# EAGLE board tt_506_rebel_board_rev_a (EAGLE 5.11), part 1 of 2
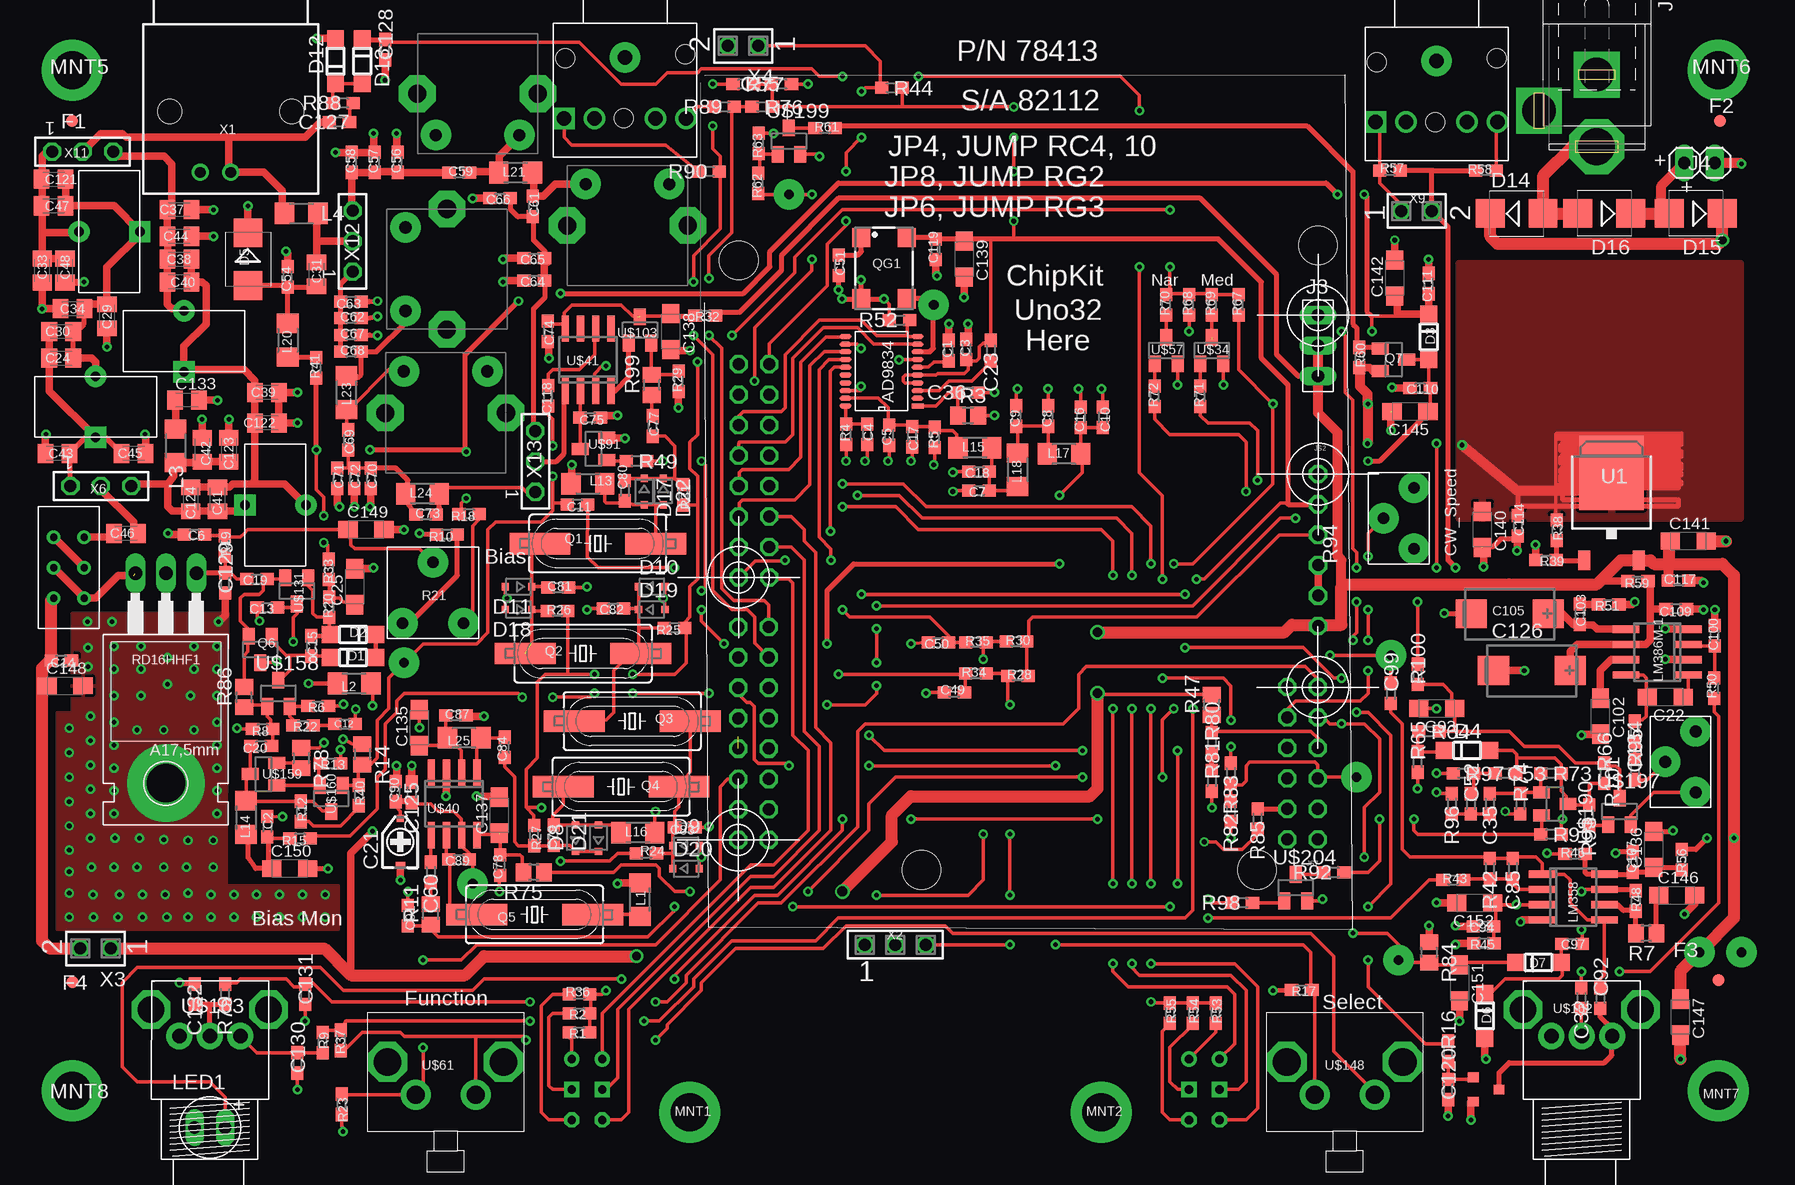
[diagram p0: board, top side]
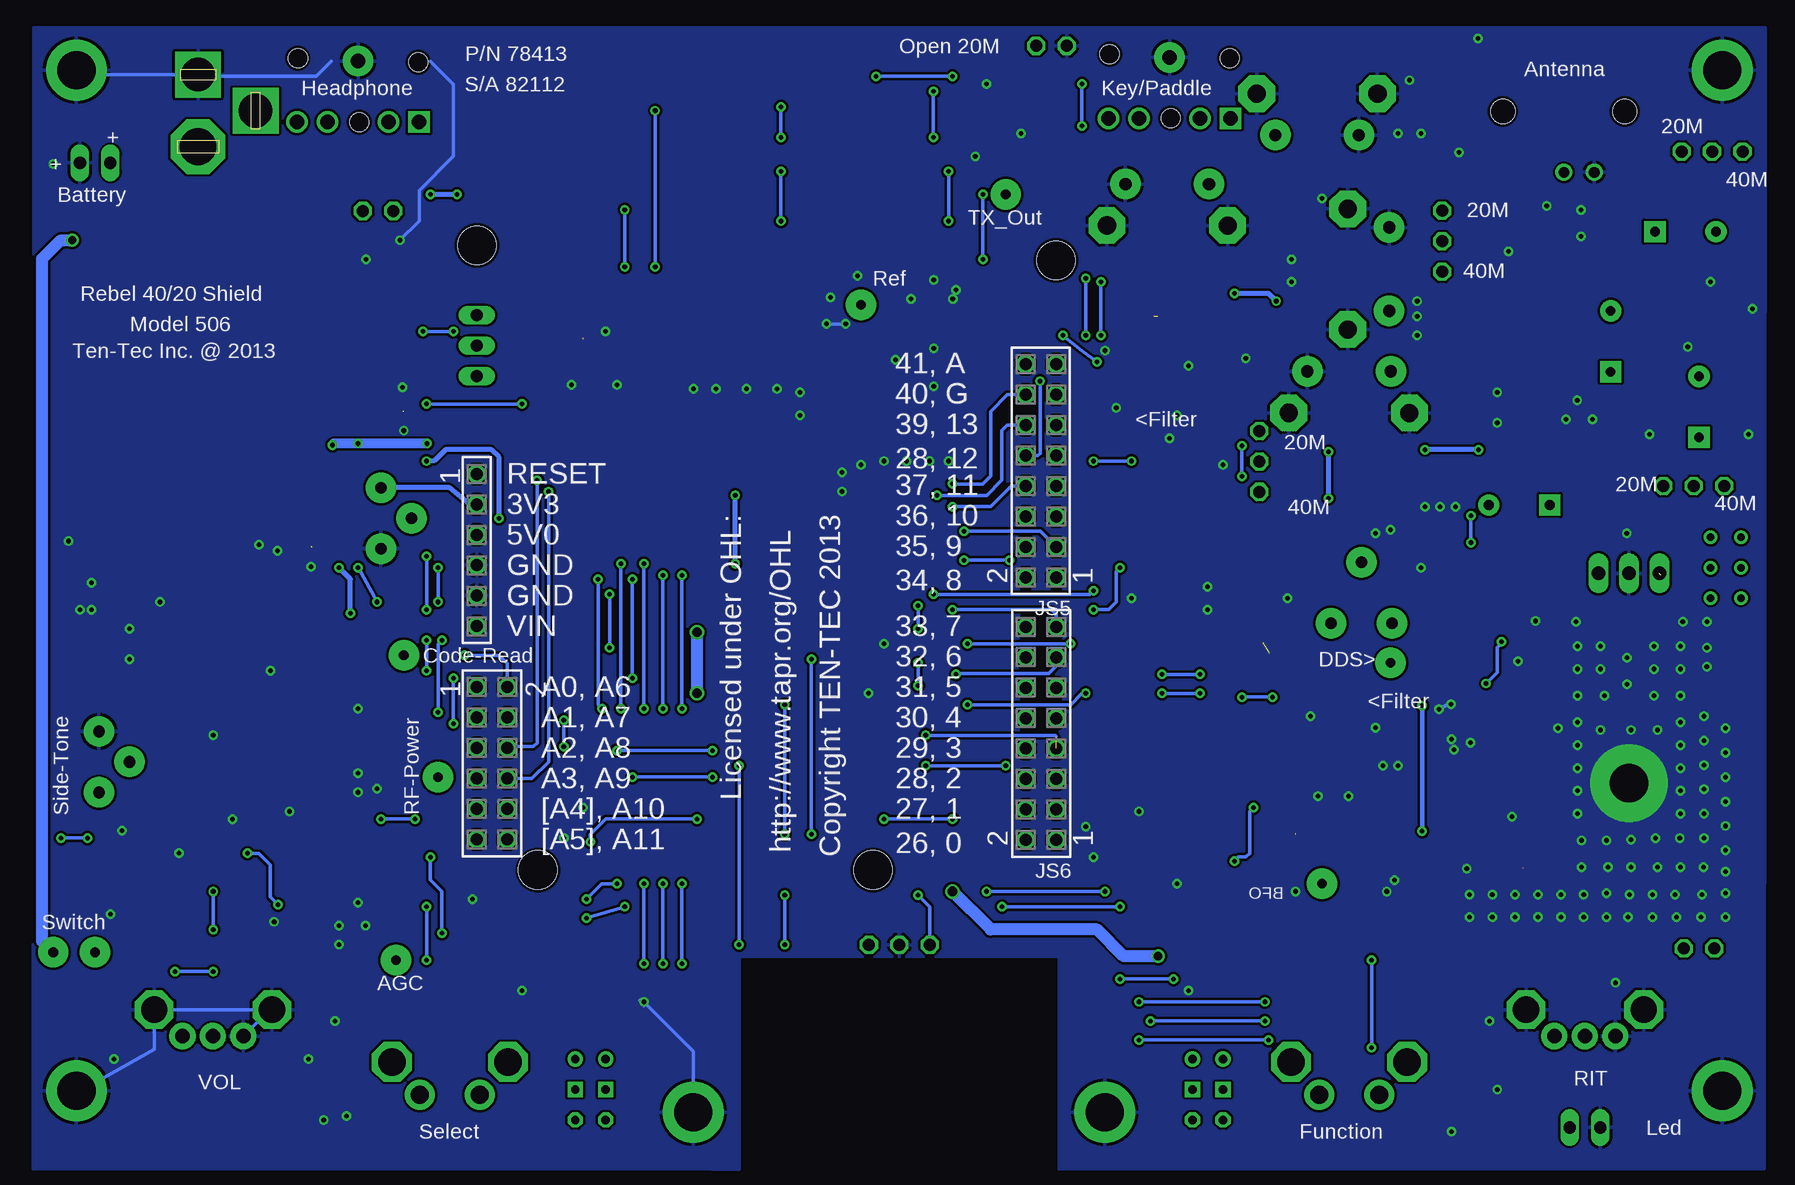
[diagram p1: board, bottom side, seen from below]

No outline drawn. Coordinates in mm, seen from the top.
Copper layers (1*16): Top 0.035mm / dielectric 1.5mm / Bottom 0.035mm
Design rules "default *": minimum track width 10mil, minimum drill 12mil, track to track 8mil, track to pad 8mil, pad to pad 8mil, via to via 8mil, smd to smd 7mil, copper to edge 10mil, drill to drill 10mil, minimum pad ring 10mil, minimum via ring 8mil, stop-mask expansion 4mil, vias tented up to drill 16mil, thermal gap 10mil
Holes 3.2 mm at 59.32,76.09 74.56,25.29 102.5,25.29 107.58,77.36

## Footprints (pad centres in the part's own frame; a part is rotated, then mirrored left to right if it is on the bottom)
0603 = smd 1.1 x 1: 1 -0.85,0; 2 0.85,0
CTRIMCTZ3 = smd 0.6 x 0.6: 1 0,1.95 | smd 0.78 x 0.6: 2 0,-1.95
SMC_A = smd 1.6 x 1.4: + -1.5,0; - 1.5,0
C0805K = smd 1.3 x 1.6: 1 -1,0; 2 1,0
POL-7343 = smd 2.6 x 2.4: + 3.2,0; - -3.2,0
SOD123 = smd 1.4 x 1.4: A 1.9,0; C -1.9,0
SMB = smd 2.4 x 2.4: A 2.2,0; C -2.2,0
SOD323-R = smd 0.6 x 0.6: A 1.1,0; C -1.1,0
FIDUCIAL-1MM = smd 1 x 1: FID 0,0
SPC4077 = drill 2.794 pad 3.81 square: 1 -3,0 | drill 2.8 pad 3.81 square: 2 0,-4.8 | drill 3.048 pad 4.572 octagon: 3 3,0
SOCKET-1X3-.1IN = drill 1.016 long: 1 -2.54,0; 2 0,0; 3 2.54,0
PINS-1X2-.1IN = drill 1.016 long: 1 -1.27,0; 2 1.27,0
SSW-106-02-S-S = drill 1 pad 1.5 octagon: 1 -6.35,0; 2 -3.81,0; 3 -1.27,0; 4 1.27,0; 5 3.81,0; 6 6.35,0
SSW-108-02-S-D = drill 1 pad 1.5 octagon: 1 -8.89,-1.27; 2 -8.89,1.27; 3 -6.35,-1.27; 4 -6.35,1.27; 5 -3.81,-1.27; 6 -3.81,1.27; 7 -1.27,-1.27; 8 -1.27,1.27; 9 1.27,-1.27; 10 1.27,1.27; 11 3.81,-1.27; 12 3.81,1.27; 13 6.35,-1.27; 14 6.35,1.27; 15 8.89,-1.27; 16 8.89,1.27
SSW-106-02-S-D = drill 1 pad 1.5 octagon: 1 -6.35,-1.27; 2 -6.35,1.27; 3 -3.81,-1.27; 4 -3.81,1.27; 5 -1.27,-1.27; 6 -1.27,1.27; 7 1.27,-1.27; 8 1.27,1.27; 9 3.81,-1.27; 10 3.81,1.27; 11 6.35,-1.27; 12 6.35,1.27
1206 = smd 1.6 x 1.8: 1 -1.4,0; 2 1.4,0
LED-.1IN = drill 1.016 long: A 1.27,0; C -1.27,0
SO08 = smd 0.6 x 2.2: 1 -1.905,-2.6; 2 -0.635,-2.6; 3 0.635,-2.6; 4 1.905,-2.6; 5 1.905,2.6; 6 0.635,2.6; 7 -0.635,2.6; 8 -1.905,2.6
MOUNTINGHOLE-.125IN = drill 3.175 pad 5.08 round: MNT 0,0
SM49 = smd 5.08 x 1.778: 1 -4.826,0; 2 4.826,0
SOT23 = smd 1 x 1.4: 1 -0.95,-1.1; 2 0.95,-1.1; 3 0,1.1
CRYSTAL_SM77H = smd 1.6 x 1.5: 1 -2.55,-1.9; 2 2.55,-1.9; 3 2.55,1.9; 4 -2.55,1.9
R0805 = smd 1.3 x 1.5: 1 -0.85,0; 2 0.85,0
RVM-06-HP03-1 = drill 0.965 pad 2.54 round: 1 -2.54,-2.54; 2 0,2.54; 3 2.54,-2.54
RVM-06-VP01-1 = drill 0.965 pad 2.54 round: 1 -2.54,-1.27; 2 0,1.27; 3 2.54,-1.27
TO-220S = drill 1.118 long: 1 -3.81,-10.16; 2 -1.27,-10.16; 3 1.27,-10.16
TOROID = drill 0.8 pad 1.778 square: P$1 0,-2.54 | drill 0.8 pad 1.778 round: P$2 0,2.54
TO252 = smd 1 x 1.6: 1 -2.28,-5.039; 3 2.28,-5.039 | smd 0.025 x 0.025: 2 0,2.261 | smd 5.4 x 6.2: 4 0,2.261
AD9834 = smd 1 x 0.406: 1 -3,2.9; 2 -3,2.25; 3 -3,1.625; 4 -3,0.975; 5 -3,0.325; 6 -3,-0.325; 7 -3,-0.975; 8 -3,-1.625; 9 -3,-2.25; 10 -3,-2.9; 11 3,-2.9; 12 3,-2.25; 13 3,-1.625; 14 3,-0.975; 15 3,-0.325; 16 3,0.325; 17 3,0.975; 18 3,1.625; 19 3,2.25; 20 3,2.9
MIKE_SOT23 = smd 1 x 1.4: 1 -0.95,-1.1; 2 0.95,-1.1; 3 0,1.1
OUT_TRI = drill 0.6 round: CLF -1.27,2.54; CLS 1.27,2.54; GRF -1.27,0; GRS 1.27,0; RDF -1.27,-2.54; RDS 1.27,-2.54
TL1105JA = drill 1.5 pad 2.5 round: 1 -2.504,0; 2 2.494,-0.01 | drill 2.3 pad 3.3 octagon: 3 -4.843,2.741; 4 4.831,2.741
10MM_CAN = drill 1.016 pad 2.54 round: 1 -3.48,3.454; 2 3.48,3.454 | drill 1.5 pad 3.048 octagon: 3 -5.029,0 | drill 1.524 pad 3.048 octagon: 4 5.029,0
35252 = drill 1.2 pad 1.778 square: 1 -5.08,5.08 | drill 1.2 pad 1.778 round: 2 -5.08,2.54; 3 -5.08,-2.54 | drill 1.2 round: 4 -5.08,-5.08 | drill 1.2 pad 2.54 round: 5 0,0 | hole 1.575: 0.254,-5.004; -0.076,5.004; -5.08,0.102
3RP/1610N = drill 1.2 pad 2.184 round: 1 -2.54,0; 2 0,0; 3 2.54,0 | drill 2.2 pad 3 octagon: 4 -4.91,2.2; 5 4.89,2.2
GYR_LED_TL = drill 0.7 pad 1.27 round: P$1 -1.27,2.54; P$2 1.27,2.54 | drill 0.7 pad 1.27 square: P$3 -1.27,0; P$4 1.27,0 | drill 0.7 pad 1.27 octagon: P$5 -1.27,-2.54; P$6 1.27,-2.54
PAD = drill 0.8 pad 2.54 round: P$1 0,0
SOT23' = smd 0.813 x 0.889: 1 -1.016,-1.079; 2 1.016,-1.079; 3 0,1.079
AMP_227161 = drill 0.9 pad 1.27 round: 1 0,-5.08; 2 -2.54,-5.08 | hole 2: -5.08,0; 5.08,0
SSW-103-02-S-S = drill 1 pad 1.5 octagon: 1 -2.54,0; 2 0,0; 3 2.54,0
SSW-101-02-S-D = drill 1 pad 1.5 octagon: 1 0,-1.27; 2 0,1.27
TSW-103-02-S-S = drill 1 pad 1.5 octagon: 1 2.54,0; 2 0,0; 3 -2.54,0

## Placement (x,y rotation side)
C1  .1uf  [0603]  76.8,68.58 90 top
C2  .1uf  [0603]  20.03,28.89 90 top
C3  .1uf  [0603]  78.3,68.68 90 top
C4  27pf  [0603]  70.01,61.59 270 top
C5  3.3pf  [0603]  71.85,61.53 270 top
C6  .1uf  [0603]  13.96,53.26 180 top
C7  tbd  [0603]  79.34,56.9 180 top
C8  3.3pf  [0603]  85.12,63.12 90 top
C9  62pf  [0603]  82.45,63.12 90 top
C10  68pf  [0603]  89.66,63.02 90 top
C11  .01uf  [0603]  45.88,55.75 0 top
C12  .01uf  [0603]  26.5,37.45 0 top
C13  .01uf  [0603]  20.02,47.16 180 top
C14  .1uf  [0603]  2.86,42.75 0 top
C15  .01uf  [0603]  23.69,43.95 270 top
C16  dni  [0603]  87.82,63.02 90 top
C17  27pf  [0603]  73.76,61.4 270 top
C18  56pf  [0603]  79.34,58.48 180 top
C19  .1uf  [0603]  19.16,49.54 180 top
C20  .1uf  [0603]  19.53,35.62 0 top
C21  2-10pf  [CTRIMCTZ3]  31.11,27.62 0 top
C22  10uf  [SMC_A]  136.53,39.69 180 top
C23  .01uf  [0603]  80.33,68.58 90 top
C24  100pf  [C0805K]  2.86,67.94 0 top
C25  10uf  [SMC_A]  27.3,48.9 90 top
C29  820pf  [C0805K]  6.67,71.44 270 top
C30  15pf  [C0805K]  2.86,70.17 0 top
C31  .01uf  [C0805K]  24.13,74.93 270 top
C32  .1uf  [0603]  129.54,14.61 90 top
C33  dni  [C0805K]  1.27,75.25 270 top
C34  dni  [C0805K]  3.81,72.07 180 top
C35  .01uf  [0603]  121.92,30.8 90 top
C36  .1uf  [0603]  78.42,65.09 0 top
C37  120pf  [C0805K]  12.7,80.33 0 top
C38  3.3pf  [C0805K]  12.7,76.2 180 top
C39  330pf  [C0805K]  20,65.09 0 top
C40  62  [C0805K]  12.7,74.3 180 top
C41  39pf  [C0805K]  15.88,56.2 90 top
C42  180pf  [C0805K]  14.61,60.33 90 top
C43  470pf  [C0805K]  2.54,60.01 180 top
C44  dni  [C0805K]  12.7,78.11 0 top
C45  dni  [C0805K]  8.89,60.01 0 top
C46  .1uf  [C0805K]  8.26,53.34 0 top
C47  120pf  [C0805K]  2.22,80.64 180 top
C48  470pf  [C0805K]  3.17,75.25 270 top
C49  .047uf  [0603]  77.28,40.1 180 top
C50  .047uf  [0603]  75.95,44.23 180 top
C51  .1uf  [0603]  67.66,75.69 270 top
C52  .01uf  [0603]  120.33,30.8 270 top
C53  .01uf  [0603]  123.19,33.34 180 top
C54  220pf  [0603]  21.73,74.73 90 top
C55  .1uf  [0603]  62.87,90.81 0 top
C56  DNI  [0603]  30.89,84.28 90 top
C57  DNI  [0603]  28.98,84.28 90 top
C58  470pf  [0603]  27.08,84.28 90 top
C59  120pf  [0603]  36.02,83.41 0 top
C60  .1uf  [0603]  33.66,25.08 90 top
C61  120pf  [0603]  42.17,80.59 270 top
C62  820pf  [0603]  27.01,71.29 0 top
C63  DNI  [0603]  27.01,72.68 0 top
C64  120pf  [0603]  42.28,74.43 180 top
C65  120pf  [0603]  42.28,76.27 180 top
C66  120pf  [0603]  39.42,81.29 180 top
C67  DNI  [0603]  27.01,69.89 0 top
C68  220pf  [0603]  27.01,68.49 0 top
C69  220pf  [0603]  26.77,61.13 270 top
C70  DNI  [0603]  28.66,57.93 270 top
C71  DNI  [0603]  25.87,57.93 270 top
C72  820pf  [0603]  27.27,57.93 270 top
C73  560pf  [0603]  33.27,54.91 0 top
C74  .1uf  [0603]  43.41,70.19 270 top
C75  .1uf  [0603]  46.94,62.99 0 top
C77  680pf  [0603]  52.15,62.29 270 top
C78  .1uf  [0603]  39.45,25.69 270 top
C79  82pf  [0603]  43.89,28.19 90 top
C80  82pf  [0603]  49.83,56.9 270 top
C81  10pf  [0603]  44.27,48.83 0 top
C82  27pf  [0603]  48.87,47.1 180 top
C83  10pf  [0603]  54.81,28.82 0 top
C84  68pf  [0603]  39.8,35.5 270 top
C85  dni  [0603]  123.83,25.4 90 top
C87  .1uf  [0603]  35.74,38.15 0 top
C89  33pf  [0603]  36,26.15 180 top
C90  56pf  [0603]  30.72,31.82 90 top
C91  .01uf  [0603]  31.74,21.47 90 top
C92  .1uf  [0603]  131.13,14.61 270 top
C93  10uf  [SMC_A]  117.47,38.73 180 top
C94  .1uf  [0603]  121.37,20.59 180 top
C97  .1uf  [0603]  128.76,19.14 180 top
C99  .1uf  [0603]  113.67,40.01 270 top
C100  2200pf  [0603]  140.65,44.81 90 top
C102  1uf  [SMC_A]  131.13,38.1 270 top
C103  .047uf  [0603]  129.39,46.6 90 top
C105  100uf  [POL-7343]  123.56,46.65 0 top
C107  .1uf  [0603]  133.83,25.95 90 top
C109  .1uf  [0603]  137.44,47.06 0 top
C110  .1uf  [0603]  116.11,65.47 180 top
C111  .1uf  [0603]  116.81,74.17 90 top
C114  .1uf  [0603]  124.24,53.98 270 top
C117  .1uf  [0603]  137.64,49.4 0 top
C118  .01uf  [0603]  43.43,64.8 90 top
C119  .1uf  [0603]  75.72,77.03 270 top
C120  .1uf  [0603]  118.43,6.99 270 top
C121  22pf  [C0805K]  2.22,82.87 180 top
C122  dni  [C0805K]  20,62.55 0 top
C123  68pf  [C0805K]  16.83,60.33 90 top
C124  12pf  [C0805K]  13.65,56.2 90 top
C125  33pf  [0603]  32.07,31.75 90 top
C126  100uf  [POL-7343]  125.41,41.91 0 top
C127  3.3pf  [0603]  26.04,87.63 0 top
C128  .1uf  [0603]  29.84,93.66 270 top
C129  22pf  [0603]  16.51,49.21 270 top
C130  .1uf  [0603]  22.54,9.21 270 top
C131  .1uf  [0603]  23.18,14.92 270 top
C132  .1uf  [0603]  13.97,14.92 90 top
C133  270pf  [C0805K]  13.34,64.45 0 top
C134  .1uf  [0603]  133.99,36.83 90 top
C135  10uf  [SMC_A]  32.7,37.15 90 top
C136  10uf  [SMC_A]  135.57,26.99 90 top
C137  10uf  [SMC_A]  39.37,29.84 90 top
C138  10uf  [SMC_A]  53.66,70.17 270 top
C139  10uf  [SMC_A]  78.11,76.2 270 top
C140  10uf  [SMC_A]  121.28,53.66 270 top
C141  10uf  [SMC_A]  138.43,52.7 0 top
C142  10uf  [SMC_A]  113.98,74.61 90 top
C145  4.7uf  [SMC_A]  115.25,63.5 180 top
C146  10uf  [SMC_A]  137.48,23.18 0 top
C147  10uf  [SMC_A]  137.79,13.02 270 top
C148  10uf  [SMC_A]  3.17,40.64 0 top
C149  10uf  [SMC_A]  28.26,53.66 0 top
C150  10uf  [SMC_A]  21.91,25.4 0 top
C151  10uf  [SMC_A]  119.38,15.88 270 top
C152  10uf  [SMC_A]  120.65,22.54 180 top
D1  MMSD914T1  [SOD123]  27.18,43 0 top
D2  MMSD914T1  [SOD123]  27.18,44.91 180 top
D3  MMSD914T1  [SOD123]  116.81,69.72 270 top
D4  MMSD914T1  [SOD123]  120.02,35.24 0 top
D5  1N4007  [SMB]  18.41,76.2 270 top
D6  MMSD914T1  [SOD123]  121.49,13.12 270 top
D7  MMSD914T1  [SOD123]  125.96,17.57 0 top
D8  BB132  [SOD323-R]  45.72,27.94 90 top
D9  BB132  [SOD323-R]  54.93,27.3 0 top
D10  BB132  [SOD323-R]  52.07,48.9 0 top
D11  BB132  [SOD323-R]  40.96,48.9 180 top
D12  MMSD914T1  [SOD123]  25.72,92.71 90 top
D13  MMSD914T1  [SOD123]  27.94,92.71 270 top
D14  1N4007  [SMB]  124.14,80.01 0 top
D15  1N4007  [SMB]  139.06,80.01 180 top
D16  dni  [SMB]  131.44,80.01 180 top
D17  BB132  [SOD323-R]  51.44,56.83 270 top
D18  BB132  [SOD323-R]  40.96,46.99 180 top
D19  BB132  [SOD323-R]  52.07,46.99 0 top
D20  BB132  [SOD323-R]  54.93,25.4 0 top
D21  BB132  [SOD323-R]  47.62,27.94 90 top
D22  BB132  [SOD323-R]  53.02,56.83 270 top
F1  FIDUCIAL1MM  [FIDUCIAL-1MM]  3.77,87.72 0 top
F2  FIDUCIAL1MM  [FIDUCIAL-1MM]  141.08,87.74 0 top
F3  FIDUCIAL1MM  [FIDUCIAL-1MM]  140.98,16.09 0 top
F4  FIDUCIAL1MM  [FIDUCIAL-1MM]  3.78,15.93 90 top
J1  [SPC4077]  130.81,88.58 270 top
J3  CONNECTOR-3SOCKET-SIL3-.1IN  [SOCKET-1X3-.1IN]  107.59,68.99 270 top
J4  CONNECTOR-2PINS-SIL2-.1IN  [PINS-1X2-.1IN]  139.38,84.23 0 top
JS2  SSW-106-02-S-S  [SSW-106-02-S-S]  107.59,51.96 270 bottom
JS5  SSW-108-02-S-D  [SSW-108-02-S-D]  60.57,58.56 90 bottom
JS6  SSW-108-02-S-D  [SSW-108-02-S-D]  60.55,36.66 90 bottom
JS7  SSW-106-02-S-D  [SSW-106-02-S-D]  106.31,34.18 270 bottom
L1  15uh  [1206]  51.08,22.82 270 top
L2  47uh  [1206]  27.27,40.83 0 top
L3  1.8uh  [1206]  12.38,60.64 90 top
L4  1uh  [1206]  22.86,80.01 180 top
L13  6.8uh  [1206]  46.74,57.48 180 top
L14  47uh  [1206]  18.26,29.65 90 top
L15  1.8uh  [1206]  78.99,60.48 0 top
L16  6.8uh  [1206]  50.91,28.41 0 top
L17  2.7uh  [1206]  86.42,59.98 0 top
L18  5.6uh  [1206]  82.55,58.64 90 top
L20  100uh  [1206]  21.74,69.44 90 top
L21  18uh  [1206]  40.72,83.41 0 top
L23  27uh  [1206]  26.64,65.07 270 top
L24  3.9uh  [1206]  32.96,56.65 0 top
L25  4.7uh  [1206]  36.44,36.31 0 top
LED1  [LED-.1IN]  15.24,3.81 0 top
LM358  LM358D  [SO08]  128.86,23.03 270 top
LM386M-1  LM386M-1  [SO08]  135.86,43.45 90 top
MNT1  MOUNTINGHOLE.125IN  [MOUNTINGHOLE-.125IN]  55.24,5.08 0 top
MNT2  MOUNTINGHOLE.125IN  [MOUNTINGHOLE-.125IN]  89.53,5.08 0 top
MNT5  MOUNTINGHOLE.125IN  [MOUNTINGHOLE-.125IN]  3.78,91.95 0 top
MNT6  MOUNTINGHOLE.125IN  [MOUNTINGHOLE-.125IN]  140.94,91.95 0 top
MNT7  MOUNTINGHOLE.125IN  [MOUNTINGHOLE-.125IN]  140.94,6.86 0 top
MNT8  MOUNTINGHOLE.125IN  [MOUNTINGHOLE-.125IN]  3.78,6.86 0 top
Q1  9.00mhz  [SM49]  47.58,52.49 180 top
Q2  9.00mhz  [SM49]  46.34,43.33 0 top
Q3  9.00mhz  [SM49]  50.44,37.69 0 top
Q4  9.00mhz  [SM49]  49.51,32.22 180 top
Q5  9.00mhz  [SM49]  42.31,21.56 180 top
Q6  MMBT3906LT1  [SOT23]  19.45,43.66 180 top
Q7  MMBT3906LT1  [SOT23]  113.89,67.82 270 top
QG1  CRYSTAL_SM77H  [CRYSTAL_SM77H]  71.41,75.44 270 top
R1  180  [0603]  46.04,11.75 180 top
R2  180  [0603]  46.04,13.34 180 top
R3  6.8k  [R0805]  78.42,63.18 0 top
R4  220  [0603]  68.29,61.59 90 top
R5  220  [0603]  75.66,61.34 90 top
R6  100  [0603]  24.28,38.94 180 top
R7  2.2k  [R0805]  134.94,20 180 top
R8  1k  [0603]  19.64,37.05 0 top
R9  100  [0603]  24.64,10.89 270 top
R10  270  [0603]  35.01,53.25 0 top
R11  560  [R0805]  33.66,21.59 90 top
R12  330  [0603]  22.83,30.16 270 top
R13  27  [0603]  25.3,34.16 180 top
R14  560  [R0805]  27.94,34.92 270 top
R15  33  [0603]  22.76,27.91 0 top
R16  10k  [0603]  118.43,10.16 270 top
R17  10k  [0603]  106.24,15.27 180 top
R18  470  [0603]  36.85,54.97 0 top
R19  220  [0603]  16.47,52.3 270 top
R20  1k  [0603]  25.21,47.19 90 top
R21  1k_TP  [RVM-06-HP03-1]  33.85,48.4 0 top
R22  10  [0603]  23.02,37.33 180 top
R23  10k  [0603]  26.23,5.75 270 top
R24  100k  [0603]  51.61,26.68 180 top
R25  100k  [0603]  53.96,45.47 0 top
R26  100k  [0603]  44.21,46.86 0 top
R27  100k  [0603]  42.27,28.16 90 top
R28  10k  [0603]  82.58,41.47 0 top
R29  1.5k  [0603]  54.31,66.01 90 top
R30  10k  [0603]  82.45,44.32 0 top
R31  100k  [0603]  54.69,56.55 90 top
R32  1k  [0603]  56.52,71.51 180 top
R33  220  [0603]  25.16,50.34 90 top
R34  100k  [0603]  79.09,41.66 0 top
R35  100k  [0603]  79.09,44.26 0 top
R36  180  [0603]  46.04,14.92 180 top
R37  10k  [0603]  26.16,11.08 270 top
R38  220  [0603]  127.48,53.59 270 top
R39  1.2k  [0603]  126.59,51.12 180 top
R40  180  [0603]  27.65,31.5 270 top
R41  470  [0603]  24.11,67.14 90 top
R42  100k  [0603]  121.92,25.4 90 top
R43  10k  [0603]  118.86,24.45 0 top
R44  10k  [0603]  72.07,90.49 180 top
R45  100k  [0603]  121.41,19.16 180 top
R46  100k  [0603]  129.02,26.61 0 top
R47  12k  [R0805]  98.74,39.05 90 top
R48  100k  [0603]  134.07,22.71 270 top
R49  10k  [0603]  50.8,59.37 180 top
R50  10k  [0603]  140.6,40.44 270 top
R51  10  [0603]  131.82,47.4 180 top
R52  DNI  [0603]  72.71,71.12 0 top
R53  180  [0603]  99.06,13.34 270 top
R54  180  [0603]  97.16,13.34 270 top
R55  180  [0603]  95.25,13.34 270 top
R56  100  [0603]  137.9,26.14 270 top
R57  100  [0603]  113.58,83.59 180 top
R58  100  [0603]  121.58,83.59 0 top
R59  100  [0603]  134.25,49.36 180 top
R60  1.5k  [0603]  111.03,68.01 270 top
R61  1.5k  [0603]  66.52,87.12 0 top
R62  1.5k  [0603]  60.96,82.52 90 top
R63  10k  [0603]  60.99,85.85 90 top
R64  10k  [0603]  116.84,36.83 180 top
R65  10k  [0603]  115.89,34.29 270 top
R66  10k  [0603]  131.44,33.34 270 top
R67  10k  [0603]  100.97,72.39 270 top
R68  1meg  [0603]  96.84,72.39 90 top
R69  4.7k  [0603]  98.74,72.39 90 top
R70  100  [0603]  94.93,72.39 90 top
R71  1k  [0603]  97.79,64.77 90 top
R72  1k  [0603]  93.98,64.77 90 top
R73  330k  [0603]  127,33.34 180 top
R74  100k  [0603]  124.46,30.8 270 top
R75  820  [R0805]  42.23,25.08 180 top
R76  10k  [0603]  61.28,88.9 180 top
R77  10k  [0603]  59.69,90.81 180 top
R78  1  [R0805]  22.86,34.61 270 top
R79  1k  [0603]  16.51,14.92 90 top
R80  1.5k  [0603]  98.74,35.88 270 top
R81  1.5k  [0603]  98.74,32.7 270 top
R82  10k  [0603]  100.33,30.16 90 top
R83  10k  [0603]  100.33,33.34 90 top
R84  150k  [R0805]  116.84,18.41 270 top
R85  180  [0603]  102.55,29.53 90 top
R86  3.3k  [R0805]  18.1,39.69 90 top
R88  1k  [0603]  26.35,89.22 0 top
R89  1k  [0603]  58.1,88.9 0 top
R90  1k  [0603]  56.83,83.5 0 top
R91  180  [0603]  127,28.26 180 top
R92  33  [0603]  108.9,25.08 0 top
R93  10k  [0603]  130.18,29.84 90 top
R94  10k_RT_TP  [RVM-06-VP01-1]  114.3,54.61 90 top
R95  10k  [0603]  133.99,33.66 270 top
R96  10k  [0603]  118.75,30.8 90 top
R97  10k  [0603]  119.7,33.34 180 top
R98  1k  [0603]  101.28,22.54 0 top
R99  47  [R0805]  52.07,65.72 90 top
R100  100  [0603]  115.89,41.59 270 top
R101  1k_RT_TP  [RVM-06-VP01-1]  137.79,34.29 90 top
RD16HHF1  TO220S  [TO-220S]  10.31,39.85 180 top
TOROID1  TOROIDGREEN  [TOROID]  6.86,78.5 90 top
TOROID2  TOROIDRED  [TOROID]  5.72,63.89 0 top
TOROID3  TOROIDBLACK  [TOROID]  13.09,69.35 0 top
TOROID4  TOROIDWHITE  [TOROID]  20.71,55.7 270 top
U1  LM1117DTX-ADJ  [TO252]  132.05,56.13 0 top
U$1  AD9834  [AD9834]  71.22,66.87 180 top
U$34  MMBT3904  [MIKE_SOT23]  98.74,68.58 0 top
U$35  [CROSS_HAIR]  59.28,27.79 0 top
U$37  OUT_TRI  [OUT_TRI]  3.49,50.48 0 top
U$40  SA612  [SO08]  35.59,30.8 180 top
U$41  SA612  [SO08]  46.77,67.82 0 top
U$56  [ARROW<--]  72.28,8.08 270 top
U$57  MMBT3904  [MIKE_SOT23]  94.93,68.58 0 top
U$60  [CROSS_HAIR]  107.59,71.53 0 top
U$61  TACT_SWITCH  [TL1105JA]  34.89,6.54 0 top
U$63  [CROSS_HAIR]  107.59,58.29 0 top
U$64  [CROSS_HAIR]  107.56,40.51 0 top
U$69  21058  [10MM_CAN]  37.55,90 180 top
U$70  21058  [10MM_CAN]  50.04,79.01 0 top
U$80  21057  [10MM_CAN]  35,75.37 90 top
U$81  21057  [10MM_CAN]  34.89,63.39 0 top
U$91  MMBT3904  [MIKE_SOT23]  47.21,60.39 90 top
U$103  MMBT3904  [MIKE_SOT23]  51.09,70.29 0 top
U$131  MMBT3904  [MIKE_SOT23]  22.48,48.55 180 top
U$143  35252R  [35252]  49.85,93.03 90 top
U$148  TACT_SWITCH  [TL1105JA]  109.82,6.54 0 top
U$157  [CROSS_HAIR]  59.3,49.68 0 top
U$158  MMBT3904  [MIKE_SOT23]  20.95,40.01 0 top
U$159  MMBT3904  [MIKE_SOT23]  19.72,33.27 90 top
U$160  MMBT3904  [MIKE_SOT23]  25.37,31.24 180 top
U$162  EVUE25POT  [3RP/1610N]  129.57,11.43 0 top
U$163  EVUE25POT  [3RP/1610N]  15.24,11.43 0 top
U$166  GYR_LED_TL  [GYR_LED_TL]  46.67,6.99 0 top
U$168  GYR_LED_TL  [GYR_LED_TL]  98.11,6.99 0 top
U$173  PAD  [PAD]  142.88,18.41 0 top
U$174  PAD  [PAD]  139.38,18.41 0 top
U$176  2N7002  [SOT23']  121.6,6.99 270 top
U$177  PAD  [PAD]  63.5,81.6 0 top
U$183  PAD  [PAD]  114.3,17.78 90 top
U$184  PAD  [PAD]  113.67,43.18 90 top
U$185  PAD  [PAD]  31.43,42.55 90 top
U$186  PAD  [PAD]  75.56,72.39 90 top
U$187  PAD  [PAD]  37.15,24.13 90 top
U$188  35252R  [35252]  117.47,92.71 90 top
U$190  MMBT3904  [MIKE_SOT23]  127.32,30.8 270 top
U$191  PAD  [PAD]  110.81,33.02 0 top
U$197  MMBT3904  [MIKE_SOT23]  132.72,30.16 0 top
U$199  MMBT3904  [MIKE_SOT23]  63.5,86.04 0 top
U$204  MMBT3904  [MIKE_SOT23]  105.73,23.81 0 top
X1  1-227161-0  [AMP_227161]  16.99,88.52 0 top
X2  SSW-103-02-S-S  [SSW-103-02-S-S]  72.36,19.05 0 top
X3  SSW-101-02-S-D  [SSW-101-02-S-D]  5.71,18.73 90 top
X4  SSW-101-02-S-D  [SSW-101-02-S-D]  59.69,93.98 90 top
X6  TSW-103-02-S-S  [TSW-103-02-S-S]  6.17,57.29 180 top
X9  SSW-101-02-S-D  [SSW-101-02-S-D]  115.81,80.23 270 top
X11  TSW-103-02-S-S  [TSW-103-02-S-S]  4.64,85.17 180 top
X12  TSW-103-02-S-S  [TSW-103-02-S-S]  27.13,77.7 270 top
X13  TSW-103-02-S-S  [TSW-103-02-S-S]  42.37,59.35 270 top

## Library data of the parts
C1-C20 C23 C32 C35 C36 C49-C75 C77-C85 C87 C89-C92 C94 C97 C99 C100 C103 C105 C107 C109-C111 C114 C117-C120 C125-C132 C134 D1-D4 D6 D7 D12 D13 F1-F4 J3 J4 L1-L4 L13-L18 L20 L21 L23-L25 LED1 MNT1 MNT2 MNT5-MNT8 Q6 Q7 R1 R2 R4-R6 R8-R10 R12 R13 R15-R46 R48-R74 R76 R77 R79-R83 R85 R88-R98 R100 R101 U1 = mike
C21 C22 C24 C25 C29-C31 C33 C34 C37-C48 C93 C102 C121-C124 C133 C135-C142 C145-C152 = rcl
D5 D8-D11 D14-D22 = diode
J1 = con-jack; OC_FARNELL: unknown; OC_NEWARK: unknown
JS2 = con-samtec; MPN: SSW-106-02-S-S; OC_FARNELL: unknown; OC_NEWARK: 11P9416
JS5 JS6 = con-samtec; MPN: SSW-108-02-S-D; OC_FARNELL: unknown; OC_NEWARK: 85K7646
JS7 = con-samtec; MPN: SSW-106-02-S-D; OC_FARNELL: unknown; OC_NEWARK: 11P9414
LM358 LM386M-1 = linear
Q1-Q5 = crystal; OC_FARNELL: unknown; OC_NEWARK: unknown
QG1 = ethernetaudioboard_revd
R3 R7 R11 R14 R47 R75 R78 R84 R86 R99 = resistor
RD16HHF1 TOROID1-TOROID4 U$1 U$37 U$40 U$41 U$69 U$70 U$80 U$81 U$143 U$158 U$166 U$168 U$173 U$174 U$176 U$177 U$183-U$188 U$191 = rebel_506
U$34 U$57 U$91 U$103 U$131 U$159 U$160 U$190 U$197 U$199 U$204 = model506_Rebel
U$35 U$60 U$63 U$64 U$157 = CROSS_HAIR
U$56 = marks
U$61 U$148 = switch
U$162 U$163 = pot
X1 = con-coax; MF: TYCO ELECTRONICS; MPN: 1-227161; OC_FARNELL: unknown; OC_NEWARK: 33B3200
X2 = con-samtec; MPN: SSW-103-02-S-S; OC_FARNELL: unknown; OC_NEWARK: 11P9367
X3 X4 X9 = con-samtec; MPN: SSW-101-02-S-D; OC_FARNELL: unknown; OC_NEWARK: 82P1456
X6 X11-X13 = con-samtec; OC_FARNELL: unknown; OC_NEWARK: unknown

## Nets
+3.3V: C3.1 C23.2 C55.1 C119.1 C139.+ JS2.2 QG1.4 R9.1 R37.1 R44.1 R76.1 R77.1 R94.3 U$1.4 U$1.5
+5.0V: JS2.3 R28.2 R30.2
+8.0V: C114.1 C140.+ Q7.2 R38.1 R60.2 R67.2 R75.1 R100.1 U1.2 U1.4
+12V: C117.1 C141.+ C147.+ J3.2 J3.3 JS2.6 L2.2 R32.1 R47.2 R56.1 R59.2 U1.3 U$174.P$1 X3.1
BAND_DETECT: JS5.16 R44.2 X4.1
BAND_END_FLASH_LED: JS7.10 R85.2
BATTERY: JS7.5 R47.1 R80.1
CODE_READ: C99.1 JS7.2 U$184.P$1
CW_SPEED: JS7.4 R94.2
ENC_A: C50.1 JS6.15 R35.1
ENC_B: C49.1 JS6.13 R34.1
FSYNC: JS5.3 U$1.15
GND: C1.2 C2.2 C3.2 C4.2 C5.2 C6.2 C7.2 C8.2 C9.2 C10.2 C12.2 C13.2 C14.2 C16.2 C17.2 C18.2 C21.2 C25.- C29.2 C33.2 C34.2 C36.2 C37.2 C39.2 C42.2 C43.2 C44.2 C45.2 C48.2 C49.2 C50.2 C51.2 C54.2 C55.2 C56.2 C57.2 C58.2 C62.2 C63.2 C64.2 C65.2 C66.2 C67.2 C70.2 C71.2 C72.2 C74.2 C75.2 C78.2 C81.2 C82.2 C83.2 C87.2 C90.2 C91.2 C93.- C94.2 C100.2 C102.- C107.2 C109.2 C110.2 C111.2 C114.2 C117.2 C119.2 C120.2 C122.2 C123.2 C125.2 C126.- C128.2 C129.2 C130.2 C131.2 C132.2 C133.2 C135.- C136.- C137.- C138.- C139.- C140.- C141.- C142.- C145.- C146.- C147.- C148.- C149.- C150.- C151.- C152.- D5.C D6.A D9.A D10.A D11.A D12.A D18.A D19.A D20.A J1.1 J4.2 JS2.4 JS2.5 L1.1 L13.2 L16.2 LED1.C LM358.4 LM386M-1.2 LM386M-1.4 MNT1.MNT MNT2.MNT MNT5.MNT MNT6.MNT MNT7.MNT MNT8.MNT Q6.3 QG1.2 R1.1 R2.1 R3.2 R4.1 R5.1 R6.1 R8.1 R10.1 R13.1 R14.1 R17.2 R23.2 R29.1 R36.1 R39.2 R45.2 R51.1 R52.1 R53.1 R54.1 R55.1 R63.2 R65.2 R68.1 R74.2 R78.1 R81.2 R82.1 R84.1 R91.1 R94.1 R96.2 R97.2 R101.3 RD16HHF1.2 U$1.7 U$1.12 U$1.18 U$34.2 U$40.3 U$41.3 U$57.2 U$69.2 U$69.3 U$69.4 U$70.2 U$70.3 U$70.4 U$80.2 U$80.3 U$80.4 U$81.2 U$81.3 U$81.4 U$91.2 U$143.5 U$162.1 U$162.4 U$162.5 U$163.1 U$163.4 U$163.5 U$176.2 U$188.5 U$199.2 U$204.2 X1.2 X2.2 X4.2
LCD_D1: JS6.6
LCD_D2: JS6.8
LCD_D3: JS6.10
LCD_D4: JS6.12
LCD_EN: JS6.4
LCD_RS: JS6.2
MEDIUM_A8: JS7.6 R71.1
MP_A: JS5.8 U$168.P$2
MP_B: JS5.12 U$168.P$4
MP_C: JS5.14 U$168.P$6
N$1: C127.1 L4.2 X1.1 X11.2
N$2: JS5.1 U$1.14
N$3: JS5.5 U$1.13
N$4: JS5.7 U$1.11
N$5: JS5.9 U$1.9
N$6: C36.1 R3.1 U$1.1
N$7: C7.1 C18.1 L15.2 L18.1
N$8: C5.1 C17.1 L15.1 R5.2 U$1.19
N$9: C4.1 R4.2 U$1.20
N$10: C1.1 U$1.6
N$11: C8.1 C9.1 L17.1 L18.2
N$12: C20.1 L14.2 R12.1 U$159.3 U$160.3
N$13: C10.1 C11.2 C16.1 L17.2
N$14: C20.2 R8.2 R86.1 U$158.1
N$15: R78.2 U$159.2
N$16: R13.2 U$159.1 U$160.2
N$17: C11.1 C118.1 R14.2 R40.1 U$160.1 U$185.P$1
N$18: R6.2 R22.2 U$158.2
N$19: C12.1 R22.1
N$20: C2.1 C150.+ L14.1 R15.1
N$21: C15.2 D1.C Q6.1 U$158.3
N$22: D1.A D2.C
N$23: C15.1 D2.A R20.1 U$131.1
N$24: C25.+ R20.2 R33.1
N$25: C32.2 R50.2
N$26: C13.1 L2.1 U$131.3
N$27: C19.1 Q6.2 R86.2 U$131.2
N$28: C46.1 U$37.CLS
N$29: R30.1 R35.2 X2.1
N$30: C6.1 C149.+ R19.1 R21.2
N$31: C19.2 C129.1 R19.2 RD16HHF1.1
N$32: R18.2 R21.3
N$33: R10.2 R21.1
N$34: R80.2 R81.1
N$35: U$37.CLF U$37.GRS
N$36: C46.2 X6.2
N$37: C24.1 C30.1 C43.1 C45.1 TOROID2.P$1 X6.1
N$38: C24.2 C29.1 C30.2 C34.1 C47.1 C121.1 TOROID1.P$1 TOROID2.P$2
N$39: C33.1 C47.2 C48.1 C121.2 TOROID1.P$2 X11.1
N$40: C41.1 C42.1 C123.1 C124.1 L3.1 TOROID4.P$1 X6.3
N$41: C38.1 C39.1 C40.1 C41.2 C122.1 C124.2 TOROID3.P$1 TOROID4.P$2
N$42: C37.1 C38.2 C40.2 C44.1 TOROID3.P$2 X11.3
N$43: R38.2 R39.1 U1.1
N$44: D4.C R64.2 R65.1
N$45: JS6.11 R17.1 U$148.1
N$46: C130.1 R9.2 U$163.3
N$47: C93.+ R64.1 R66.1 R100.2 U$197.3
N$48: R61.1 U$199.3
N$49: C100.1 LM386M-1.3 R50.1
N$50: C35.2 R73.2 R74.1 U$190.1
N$51: C31.1 L4.1 X12.2
N$52: C31.2 C54.1 D5.A L20.2
N$53: L20.1 R41.2
N$54: R1.2 U$166.P$1
N$55: C61.2 C64.1 C65.1 C66.1 X13.3
N$56: C56.1 C57.1 C58.1 C59.1 X12.3
N$57: C59.2 L21.1 U$69.1
N$58: C61.1 L21.2 U$70.1
N$59: C62.1 C63.1 C67.1 C68.1 X12.1
N$60: C68.2 L23.1 U$80.1
N$61: C69.1 L23.2 U$81.1
N$62: C69.2 C70.1 C71.1 C72.1 C73.1 L24.1
N$63: C73.2 L24.2 X13.1
N$64: U$41.1 X13.2
N$65: C80.2 D17.A D22.A L13.1 Q1.1
N$66: U$41.4 U$103.1
N$67: R29.2 R99.2 U$103.2
N$68: C74.1 C138.+ R32.2 U$41.8 U$103.3
N$69: C75.1 U$41.2 U$91.3
N$70: C127.2 R88.2
N$71: C83.1 D9.C D20.C Q3.2 Q4.1 R24.1
N$72: R24.2 R25.2 R26.2 R27.2 R31.1 R67.1 R68.2 R69.2 R70.2
N$73: C81.1 D11.C D18.C Q1.2 Q2.1 R26.1
N$74: C79.2 D8.A D21.A L16.1 Q4.2
N$75: C77.2 C80.1 D17.C D22.C R31.2
N$76: C79.1 C84.2 D8.C D21.C R27.1
N$77: C60.1 R11.2
N$78: C14.1 C148.+ U$37.RDF X3.2
N$79: JS6.5 R23.1 U$61.1
N$80: QG1.3 U$1.8 U$186.P$1
N$81: C84.1 L25.2 U$40.1
N$82: C21.1 C89.1 C90.1 C125.1 U$40.7 U$187.P$1
N$83: C78.1 C137.+ R75.2 U$40.8
N$84: C89.2 Q5.2 U$40.6
N$85: R12.2 R40.2
N$86: C60.2 U$40.5
N$87: C85.1 LM358.2 R42.1 R43.2
N$88: C51.1 QG1.1
N$89: LM358.6 R7.2 R48.2
N$90: C91.1 R11.1 R43.1
N$91: C85.2 C92.1 C99.2 LM358.1 LM358.5 R42.2
N$92: C94.1 C152.+ LM358.3 R45.1 R46.1
N$93: C97.1 LM358.7 R48.1
N$94: C146.+ R7.1
N$95: C97.2 D6.C D7.A
N$96: R49.2 U$91.1
N$97: C92.2 U$162.3 U$176.3
N$98: R28.1 R34.2 X2.3
N$99: R37.2 U$61.2 U$148.2
N$100: C103.1 C105.+ LM386M-1.5
N$101: C22.- C134.2 LM386M-1.8
N$102: C22.+ LM386M-1.1
N$103: C102.+ LM386M-1.7
N$104: C103.2 R51.2
N$105: D14.C D15.C U$173.P$1
N$106: R2.2 U$166.P$3
N$107: C107.1 C136.+ LM358.8 R46.2 R56.2
N$108: JS5.11 R52.2 U$1.10
N$109: R36.2 U$166.P$5
N$110: R53.2 U$168.P$1
N$111: R54.2 U$168.P$3
N$112: R55.2 U$168.P$5
N$113: R89.1 U$143.4
N$114: R57.2 U$188.1 X9.1
N$115: C105.- R57.1 R58.1 X9.2
N$116: R58.2 U$188.4
N$117: C109.1 C126.+ LM386M-1.6 R59.1
N$118: R69.1 U$34.3
N$119: C87.1 C135.+ L25.1 U$40.2
N$120: R70.1 U$57.3
N$121: Q7.1 R60.1 R61.2
N$122: C118.2 U$41.6
N$123: L1.2 Q5.1
N$124: R62.2 R63.1 U$199.1
N$125: R71.2 U$34.1
N$126: R72.2 U$57.1
N$127: C35.1 C52.2 R96.1
N$128: C120.1 R16.2 U$176.1
N$129: C32.1 U$162.2
N$130: C23.1 U$1.3
N$131: C128.1 D13.C R83.2
N$132: D14.A D16.A J1.3
N$133: LED1.A R85.1
N$134: D15.A D16.C J4.1
N$135: C132.1 R79.1 U$163.2
N$136: C133.1 L3.2
N$137: D12.C D13.A R88.1
N$139: R90.1 U$143.1
N$140: R92.1 U$204.3
N$141: RD16HHF1.3 U$37.GRF U$37.RDS
N$142: R91.2 R92.2 U$190.2
N$143: C53.1 D4.A R66.2 R73.1 R93.2 U$190.3
N$144: R93.1 U$197.1
N$145: R101.1 U$197.2
N$146: R95.2 R101.2
N$147: C134.1 R95.1
N$148: C52.1 C53.2 R97.1
N$149: C77.1 R99.1
N$150: R98.2 U$204.1
N$152: C82.1 D10.C D19.C Q2.2 Q3.1 R25.1
NARROW_A9: JS7.8 R72.1
POWER_OUT: JS7.7 R82.2 R83.1 U$191.P$1
RESET: JS2.1
RIT: C131.1 JS7.1 R79.2
S_METER: C151.+ D7.C JS7.3 R49.1 R84.2 U$183.P$1
SELECT_GREEN: JS5.2 U$166.P$2
SELECT_RED: JS5.6 U$166.P$6
SELECT_YELLOW: JS5.4 U$166.P$4
SIDETONE: JS6.7 R98.1
T: C110.1 C145.+ D3.A Q7.3 R15.2
TD: C111.1 C142.+ D3.C R16.1 R18.1 R33.2 R41.1
TX_IN_DAH: JS6.16 R76.2 R89.2
TX_IN_DIT: JS6.14 R77.2 R90.2
TX_OUT: JS5.10 R62.1 U$177.P$1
